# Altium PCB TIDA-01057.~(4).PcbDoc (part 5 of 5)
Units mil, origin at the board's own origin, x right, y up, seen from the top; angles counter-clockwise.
Board outline 4448 x 3930 mil, 4 copper layers (Layer 1 - Top Layer, Layer 2 - GND, Layer 3 - PWR, Layer 4 - Bottom Layer), stack 59.034 mil thick; 537 components, 284 nets, 1540 pads, 770 vias.
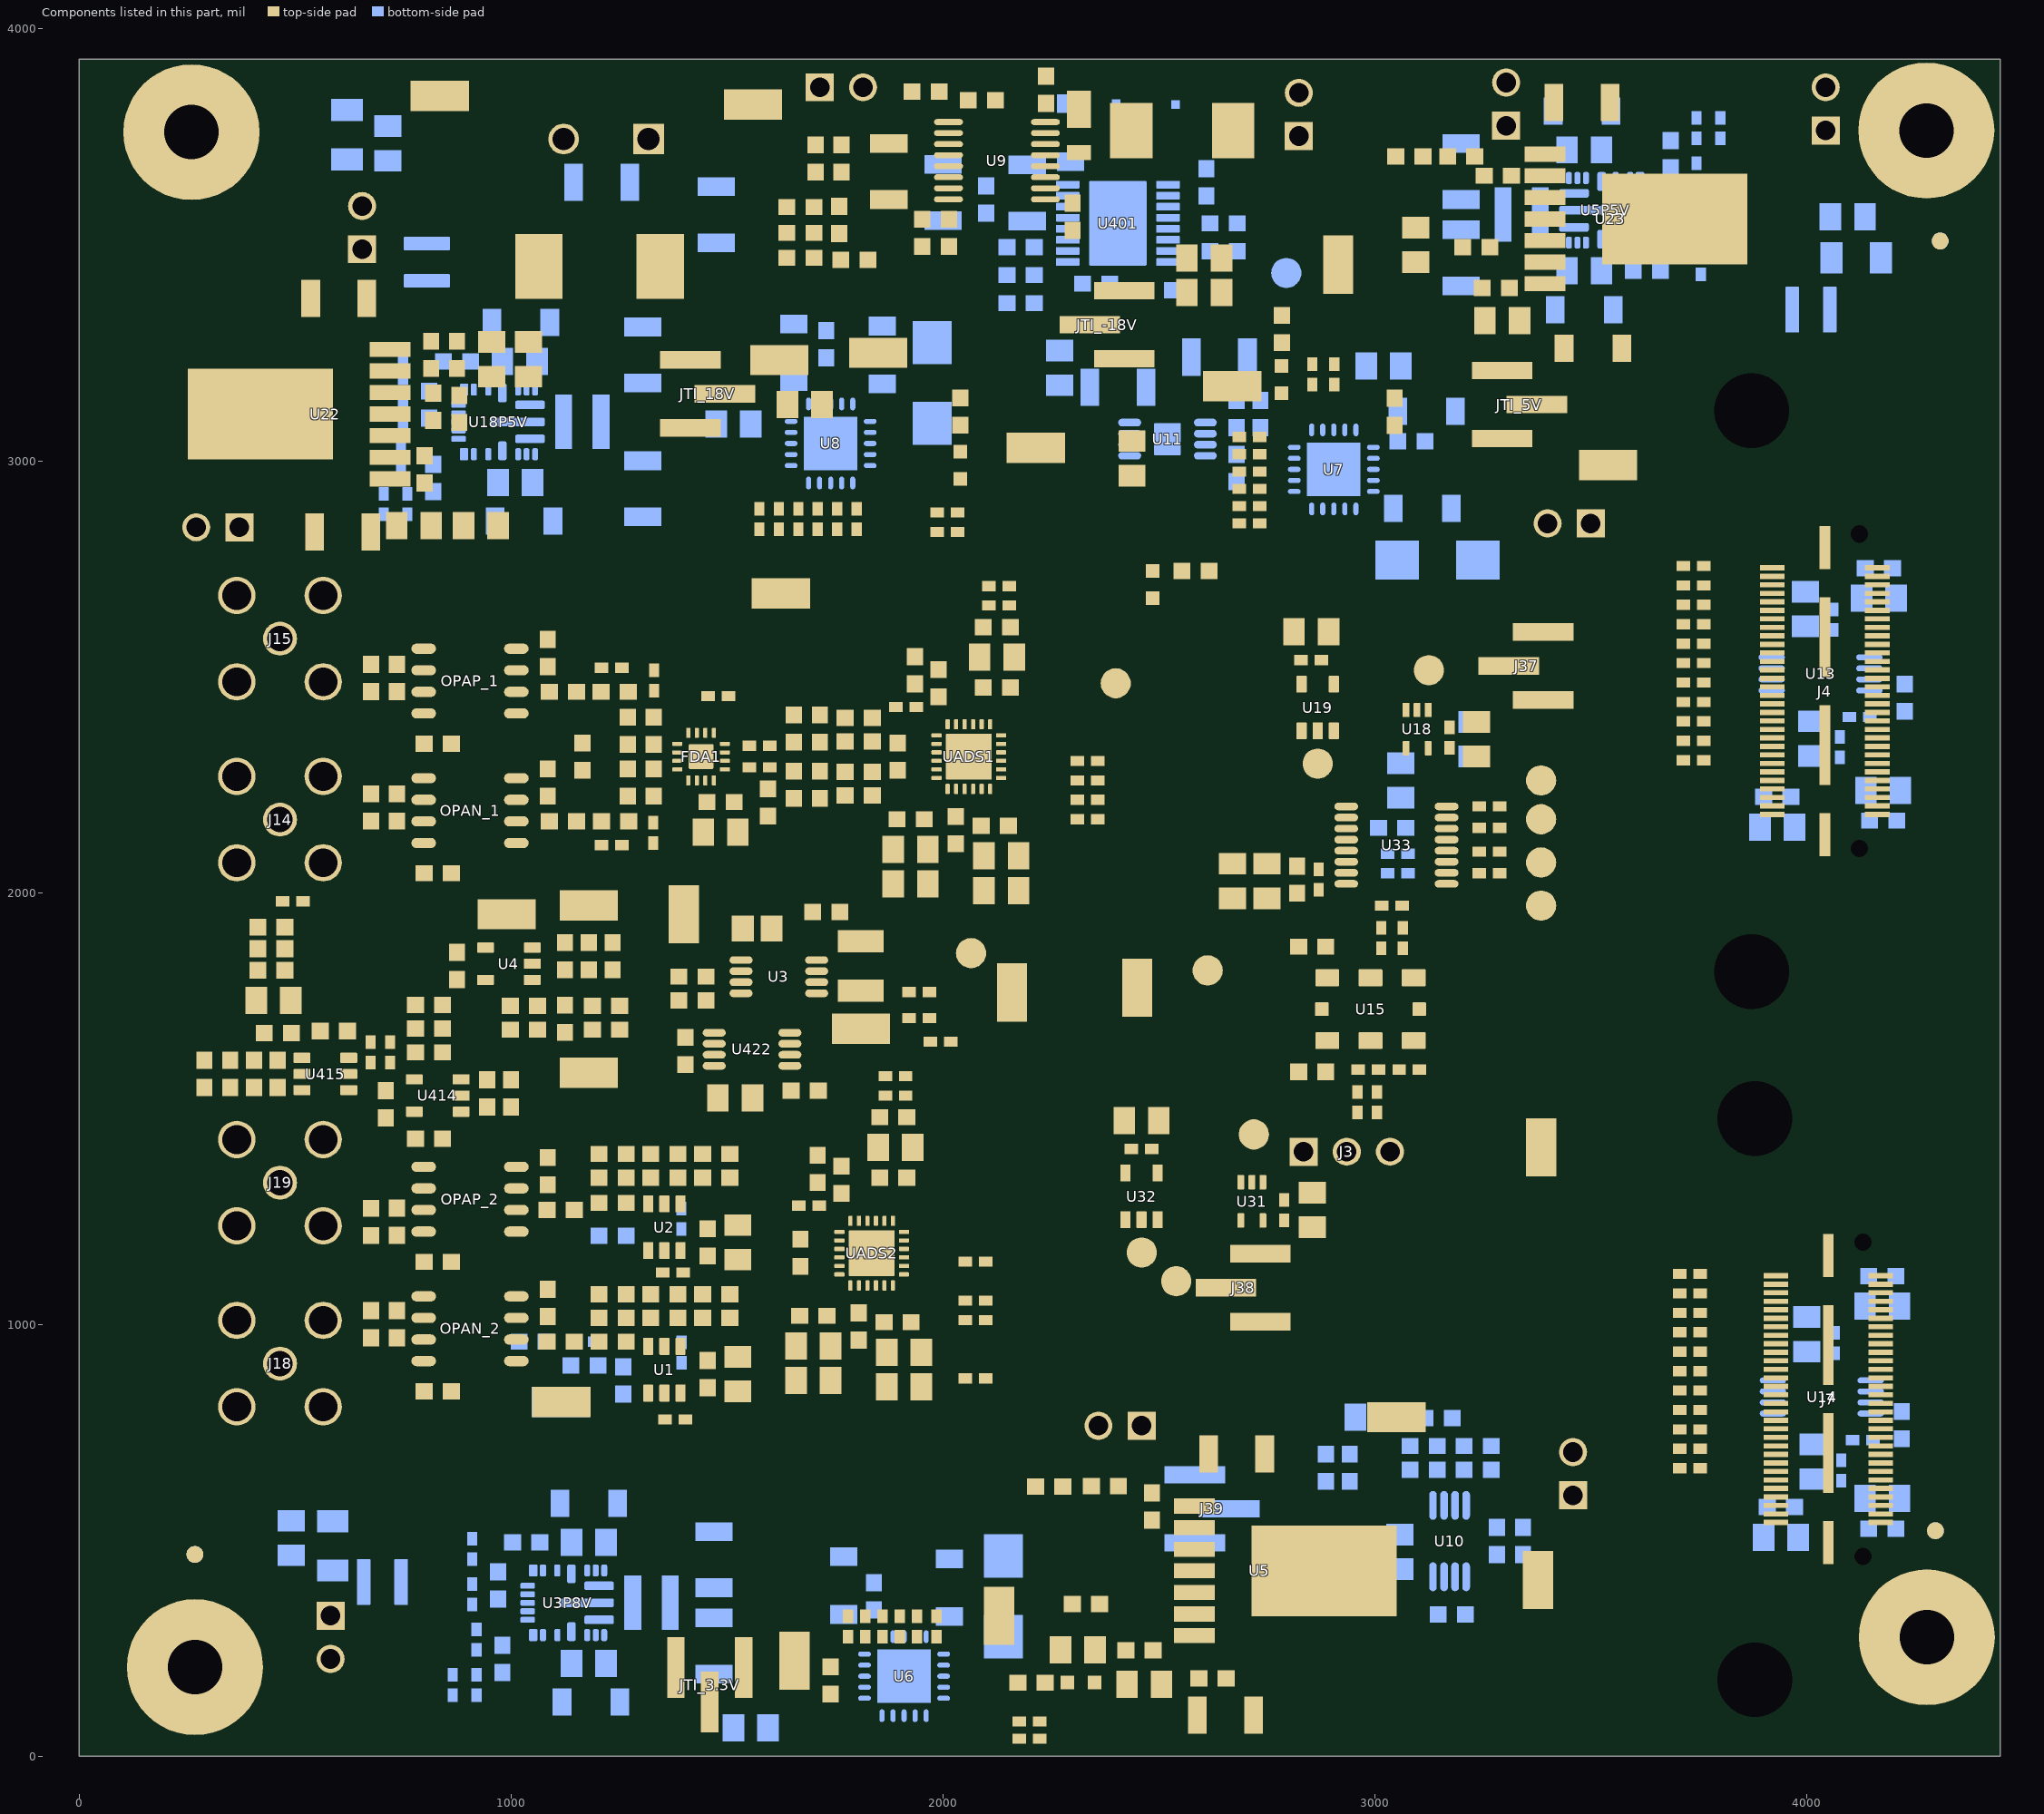
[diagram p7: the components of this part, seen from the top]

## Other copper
Layer 1 - Top Layer:
  rectangle net NetC40_2: 2219,3779 2257.6,3847
  rectangle net +18V: 1975,3110 2075,3190
  rectangle net NetC387_2: 1159.96,3025 1385,3150
  rectangle net NetC363_2: 1385,315 1510,395
  rectangle net NetJTI_3.3V_2: 1370,25 1490,120
  rectangle net 3.8V: 1629,240 1762,290
  region net PRE: 2205,3770.85 2205,3722 2272,3722 2279,3729 2279,3738 2441,3738 2441,3829.79 2376.21,3829.79 2293,3913 2291,3911 2217,3911 2217,3862.32 2220.32,3859 2284,3859 2284,3854 2284,3772
  region net GND: 2249.49,3669 2277,3669 2297,3689 2552,3689 2552,3646 2549,3643 2548.1,3643.9 2264.1,3643.9 2249.49,3643.9
  region net GND: 3335,3580 3288,3580 3288,3547 3115,3547 3108.55,3540.55 3146.59,3502.5 3214.48,3502.5 3234.49,3519 3317.54,3519 3335,3536.46
  region net NetC452_1: 439,1943 352,1943 352,1649 351,1648 256,1648 256,1588 261,1583 263,1585 431,1585 431,1638.78 442.22,1650 452,1650 452,1703 439,1716
  region net GND: 1660,3490 1660,3445 1540,3445 1540,3655 1605,3655 1605,3490
  region net NetC403_2: 2350,3260 2350,3210 2560,3210 2575,3225 2575,3345 2445,3345 2430,3330 2430,3260
  region net NetJTI_-18V_2: 2420,3340 2420,3295 2405,3280 2300,3280 2300,3225 2145,3225 2145,3320 2165,3340
  region net 1050_-18V: 2590,3505 2590,3355 2270,3355 2270,3555 2330,3555 2330,3425 2540,3425 2540,3505
  region net GND: 2525,3831 2774,3831 2774,3650 2838,3650 2838,3515 2774,3515 2679,3515 2679,3355 2610,3355 2605,3360 2605,3515 2555,3515 2525,3545
  region net GND: 925,3220 1090,3220 1130,3180 1130,2820 940,2820 940,2885 1030,2885 1030,2990 1030,3161 925,3161
  region net GND: 210,2925.6 386.4,2925.6 520,2792 570,2792 570,2880 527,2880 527,2965 590,2965 590,3085 790,3085 800,3075 843.78,3075 921.89,2996.89 921.89,2928 1035,2928 1035,3221 907.2,3221 907.2,3125.64 590.86,3129.15 585,3135 585,3435 547.5,3465 290,3465 210,3385
  region net 1050_18V: 640,3420 740,3420 740,3295 790,3295 790,3325 1093.18,3325 1123.18,3270 1245,3270 1255,3260 1505,3260 1505,3195 1415,3195 1415,3205 1350,3205 1350,3195 1335,3180 1140,3180 1140,3200 1095,3245 905,3245 895,3255 790,3255 775,3240 640,3240
  region net AGND: 862.87,1539.75 965,1539.75 965,1409.75 925,1409.75 840,1409.75 840,1449.75 925,1449.75 925,1519.75 862.87,1519.75
  region net REFOUT: 1690,1509.75 1690,1719.75 1880,1719.75 1880,1649.75 1755,1649.75 1750,1644.75 1750,1509.75
  region net AGND: 1510,1609.75 1430,1609.75 1415,1624.75 1340,1624.75 1340,1559.75 1410,1489.75 1510,1489.75
  region net 5V: 1433.54,1694.75 1433.54,1639.75 1340,1639.75 1340,1694.75
  region net 5V: 1563,1817.75 1554,1808.75 1511,1808.75 1410,1909.75 1410,2014.75 1563,2014.75
  region net 5V: 1915,1984.75 1845,1984.75 1835,1994.75 1835,2041.75 1845,2051.75 1915,2051.75
  region net 3.3V: 2053.93,291.07 2053.93,177.07 2083.93,147.07 2193.93,147.07 2193.93,291.07
  region net VDDO: 3194,2062.75 3092,2062.75 3075,2079.75 3075,2159.75 3099,2183.75 3194,2183.75 3194,2164.75 3128,2164.75 3115,2151.75 3115,2091.75 3126,2080.75 3194,2080.75
  region net -18.5V: 2125,3072.5 2125,2977.5 2125,2912.5 2260,2912.5 2260,2977.5 2360,2977.5 2360,3072.5
  region net 3.3V: 2732.21,1257.75 2732.21,1222.75 2760.21,1194.75 2900.21,1194.75 2910.21,1204.75 2910.21,1250.75 2903.21,1257.75
  region net GND: 2775.21,1269.75 2900.21,1269.75 2910.21,1279.75 2910.21,1329.75 2900.21,1339.75 2810.21,1339.75 2775.21,1304.75
  region net 3.3V: 2453,1326.3 2453,1516.75 2438.45,1531.3 2391.55,1531.3 2380,1519.75 2380,1356.13 2409.83,1326.3
  region net GND: 2466.83,1393.3 2501.83,1393.3 2529.83,1421.3 2529.83,1521.3 2519.83,1531.3 2480.83,1531.3 2466.83,1517.3
  region net 3.3V: 3114.81,2351.57 3272.81,2351.57 3272.81,2278.57 3257.81,2263.57 3144.81,2263.57 3114.81,2293.57
  region net GND: 2859.81,2525.57 2894.81,2525.57 2922.81,2553.57 2922.81,2656.94 2915,2664.75 2870,2664.75 2859.81,2654.55
  region net 3.3V: 2847.81,2458.57 2847.81,2656.94 2840,2664.75 2780,2664.74 2772.81,2657.55 2772.81,2503.57 2817.81,2458.57
  region net AGND: 1731.37,1808.16 1731.37,1975.16 1596.79,1975.16 1576.79,1955.16 1576.79,1868.16 1636.79,1808.16
  region net NetC5_2: 1863.15,1859.75 1863.15,1881.6 1863.15,1914.75 1817.31,1914.75 1775,1974.75 1740,1974.75 1740,1859.75
  region net NetC5_1: 1680.79,1802.16 1870,1802.16 1870,1734.75 1701.2,1734.75 1680.79,1755.16
  region net AGND: 1403.79,1829.16 1409.79,1823.16 1409.79,1730.16 1355.79,1730.16 1344.79,1741.16 1344.79,1770.16 1344.79,1819.75 1354.2,1829.16
  region net AGND: 1210,1715.01 1170,1715.01 1165,1720.01 1165,1760.01 1150,1775.01 1105,1775.01 1090,1790.01 1090,1811.01 1079,1822.01 1029,1822.01 1029,1847.01 1193,1847.01 1200,1840.01 1200,1790.01 1210,1780.01
  region net 5V: 1380,1179.75 1580,1179.75 1580,1124.75 1380,1124.75
  region net AGND: 1580,1199.75 1435,1199.75 1435,1239.75 1455,1259.75 1570,1259.75 1580,1249.75
  region net +24VDC: 1295,3360 1500,3360 1500,3515 1295,3515
  region net AGND: 1988,902.74 1995,909.75 1995,979.74 1950,1024.74 1914.45,1024.74 1905,1024.74 1905,984.75 1925,964.75 1925,902.74
  region net 5V: 1380,859.75 1395,874.75 1576.87,874.75 1610,901.75 1613.12,835.08 1580,819.75 1380,819.75
  region net AGND: 1580,894.75 1435,894.75 1435,934.75 1455,954.75 1570,954.75 1580,944.75
  region net AGND: 1610,917.75 1610,1014.75 1635,1039.75 1690,1039.75 1690,917.75
  region net 5V: 1610,834.75 1690,834.75 1690,901.75 1610,901.75
  region net NetC119_1: 1780,1102.75 1780,1009.75 1785,1004.75 1795,1004.75 1825,1004.75 1825,1054.75 1811,1068.75 1811,1102.75
  region net 3.3V: 1985,819.74 1925,819.74 1925,886.74 1982.45,886.74 1994.45,874.75 1994.45,829.19
  region net AGND: 1895,1319.75 1945,1319.75 1975,1349.75 1975,1444.75 1895,1444.75
  region net VDD: 2962,2036.75 2726,2036.75 2718,2044.75 2718,2112.75 2788,2182.75 2962,2182.75 2962,2112.75 2898,2112.75 2885,2099.75 2885,2069.75 2900,2054.75 2962,2054.75
  region net GND: 2635.01,2039.75 2635.01,2114.75 2645.01,2124.75 2692.01,2124.75 2702.01,2114.75 2702.01,2039.75
  region net 3.3V: 2635.01,2014.75 2635.01,1944.75 2645.01,1934.75 2775.01,1934.75 2785.01,1944.75 2785.01,2014.75
  region net 5V: 1475,2271.75 1475,2109.75 1465,2099.75 1395,2099.75 1395,2214.75 1405,2224.75 1405,2271.75
  region net AGND: 1495,2229.75 1495,2109.75 1505,2099.75 1580,2099.75 1615,2134.75 1615,2199.75 1570,2199.75 1560,2209.75 1560,2229.75
  region net NetFDA1_13: 1475,2357.75 1475,2469.75 1425,2469.75 1405,2449.75 1405,2357.75
  region net AGND: 1835,2067.75 1835,2164.75 1860,2189.75 1915,2189.75 1915,2067.75
  region net NetC88_2: 2005,2252.75 2005,2159.75 2010,2154.75 2020,2154.75 2050,2154.75 2050,2204.75 2036,2218.75 2036,2252.75
  region net AGND: 2219.45,2052.74 2219.45,2149.74 2194.45,2174.74 2139.45,2174.74 2130,2174.74 2130,2134.75 2150,2114.75 2150,2052.74
  region net 3.3V: 2220,1972.75 2150,1972.75 2150,2036.74 2220,2036.74
  region net AGND: 2135,2454.75 2185,2454.75 2215,2484.75 2215,2579.75 2135,2579.75
  region net GND: 3157.81,2365.54 3272.81,2365.54 3272.81,2485.04 3210,2485.04 3157.81,2432.85
  region net GND: 4045.03,1236.69 4065.03,1236.69 4065.03,1101.69 4095.03,1071.7 4095.03,576.7 4065.03,546.7 4065.03,416.69 4045.03,416.7 4035.03,426.7 4005.03,456.69 4005.03,1196.69 4035.03,1226.69
  region net GND: 2400,2992.5 2475,2992.5 2490,3007.5 2490,3082.5 2500,3092.5 2540,3092.5 2551.07,3081.43 2551.07,3018.57 2574.79,2994.85 2589.79,2979.85 2589.79,2933.5 2400,2933.5
  region net GND: 4036.51,2056.79 4056.51,2056.79 4056.51,2191.78 4087.01,2222.28 4087.01,2716.29 4056.51,2746.78 4056.51,2876.79 4036.51,2876.78 4026.51,2866.78 3996.52,2836.79 3996.52,2096.79 4026.51,2066.79
  region net 5V: 1392.4,840.61 1410,823.01 1410,786.12 1403.62,779.75
  region net 5V: 597.5,1639.75 682.5,1639.75 682.5,1714.75 597.5,1714.75
  region net AGND: 822.5,1754.75 905,1754.75 905,1664.75 822.5,1664.75
  region net GND: 2870,3585 3015,3585 3015,3515 3130,3515 3130,3562.78 3075,3587.22 3075,3725 3020.02,3725 3020.02,3695 2870,3695
  region net 1050_-18V: 1830,3600 1920,3600 1920,3520 2092,3520 2092,3865 2175,3865 2175,3520 2300,3520 2300,3454 1805,3454 1805,3485 1830,3485
  region net NetC31_1: 1675.16,3905.16 1675,3705 1925,3705 1925,3815 1760.02,3815 1760.08,3905.16
  region net NetCin3_1: 2419.84,815 2419.84,690.84 2407,678 2379,678 2379,592 2379,580 2387,580 2524,580 2525,579 2525,561 2656,561 2657,561 2660,563 2660,759 2532,759 2532,763 2532,766 2532,815
  region net 1050_3.3V: 2630,294 2630,217 2611,198 2611,30 2480,30 2480,212 2466,226 2466,263 2503,263 2536,296
  region net GND: 3089,535 2855.7,615 2773,615 2773,757 2699,757 2699,535 2699,474 2674,449 2555,449 2530,449 2365.83,449 2281.76,520 2277.5,586.5 2252,599 2233,599 2233,615 2212.4,615 2197,615 2197,565.88 2235.88,565.88 2237.76,200 2306.76,200 2306.76,353.61 2366.15,413 2535.2,413 2654,413 2654,50 2814,50 3089,325
  region net 1050_3.3V: 1508.67,265 1588.67,265 1588.67,157.84 1683.5,63 1693,63 1832,63 1839.91,50 1964.67,50 1964.67,10 1508.67,10
  region net NetCin2_1: 3465,3875 3465,3685 3335,3685 3275,3685 3275,3640 3210,3640 3210,3829.96 3344.96,3829.96 3390,3875
  region net 1050_5V: 3445,3430 3290,3430 3290,3370 3300,3360 3300,3275 3270,3275 3225,3230 3225,3185 3455,3185 3460,3190 3460,3315 3445,3330
  region net GND: 3890,3665 3890,3740 3857.34,3740 3857.34,3665 3639.69,3665 3639.33,3664.65 3595,3708.98 3595,3875 3484.67,3875 3485.39,3580 3335,3580 3335,3540 3484.67,3540 3484.67,3220 3520.63,3220 3595,3220 3595,3385 3665,3455 3857.34,3455 3857.34,3414.69 3890,3414.69
  region net NetJTI_5V_2: 3445,3095 3155,3095 3155,3185 3035,3185 3035,3275 3040,3280 3185,3280 3210,3255 3210,3180 3220,3170 3445,3170
  region net NetC374_2: 3210,3085 3210,3015 3215,3010 3435,3010 3465,3040 3695,3040 3695,3205 3470,3205 3470,3180 3460,3170 3460,3085
  region net NetC363_2: 1355,395 1355,135 1410,135 1410,395
  region net NetJTI_18V_2: 1565,3175 1420,3175 1420,3105 1495,3105 1495,3050 1565,3050 1565,3105
  region net 18.5V: 1553,3278 1548,3273 1548,3195.46 1703.46,3195.46 1711,3203 1711,3265.5 1698.5,3278
  region net NetCin1_1: 670,2980 665.8,2980 665.8,3055 596.03,3055 596.03,2933.55 665.8,2933.55 675,2924.35 675,2906.74 650,2881.74 650,2790 765,2790 765,2915 820,2915 820,2980
  text ".Layer_Name" at 57,-1078.49 h60
Layer 2 - GND:
  pour cut-out: 205.85,2897.37 410,2897.37 410,2894.99 480,2824.99 480,2780 212.11,2780 205,2787.11
  text ".Layer_Name" at 57,-1078.49 h60
Layer 3 - PWR:
  rectangle net +24VDC: 1390,3365 1493,3535
  rectangle net +18V: 1925,3115 2025,3190
  region net NetC387_2: 1385,3140 1225,3140 1225,3035 1385,3035
  rectangle net NetC374_2: 3130,3515 3285,3620
  rectangle net NetC381_1: 509,2880 579,2966
  rectangle net NetC401_1: 2617,3676 2886,3795
  rectangle net NetC374_2: 3495,3075 3685,3205
  rectangle net 1050_3.3V: 1790,0 2624,50
  rectangle net 1050_3.3V: 1975,45 2624,96
  rectangle net NetCin1_1: 330,2795 410,2870
  region net GND: 1265,3625 1435,3625 1470,3660 1470,3740 1435,3775 1265,3775
  text ".Layer_Name" at 57,-1078.49 h60
Layer 4 - Bottom Layer:
  rectangle net GND: 3585.29,3637 3637,3657.8
  rectangle net NetC367_1: 4010,3285 4090,3810.08
  rectangle net GND: 690,3025 729.5,3090
  rectangle net GND: 3760,3575 3800,3635
  rectangle net GND: 865,295 895,355
  rectangle net GND: 3415,3610 3434.61,3620
  rectangle net GND: 3585,3636.75 3603,3727.21
  rectangle net GND: 1061,214 1081,328
  rectangle net GND: 902,2825 920,2969.61
  region net NetC403_2: 2475,3655 2335,3655 2335,3450 2475,3450
  rectangle net NetJTI_5V_2: 3035,3185 3160,3275
  rectangle net NetC357_1: 1120,400 1155,505
  rectangle net NetC363_2: 1355,295 1528.31,415
  rectangle net NetC357_1: 1095,210 1155,315
  region net NetC374_2: 3320,3635 3145,3635 3145,3505 3320,3505
  region net NetC369_1: 3570,3700 3505,3700 3505,3620 3570,3620
  region net NetC369_1: 3545,3535 3510,3535 3510,3445 3545,3445
  rectangle net NetC387_2: 1154.96,3020 1345,3145
  rectangle net NetC381_1: 965,3115 995,3205
  rectangle net NetC381_1: 940,2890 995,3030
  rectangle net NetC387_2: 1205,2955 1315,3030
  rectangle net NetC387_2: 1235,3125 1340,3185
  rectangle net NetJTI_18V_2: 1445,3040 1520,3140
  region net GND: 3004,484 3004,583 3000,587 2955,587 2955,486.52 2957.52,484
  region net -0.2V: 2985,825 2865,825 2661.88,680 2510,680 2510,625 2730,625 2865,680 2985,680
  region net GND: 4105,3611.19 4105,3290 4200,3290 4215,3305 4210,3580 4160,3600
  region net GND: 880,3030 905,3030 905,3050 925,3050 925,3000 880,3000
  region net 5V: 910,1773.98 910,1829.75 985,1829.75 985,1773.98
  region net -18V: 2635,3110 2763.54,3110 2763.54,3227.46 2763.54,3295.12 2610,3295.12 2610,3145 2578.96,3145 2578.96,3082.29 2635,3082.29
  region net GND: 2416,3136 2416,3127.95 2470,3127.95 2470,2925 2708.54,2925 2708.54,2978.54 2640,2978.54 2640,3020 2560,3020 2560,3155 2600,3155 2600,3234 2600,3285.12 2565.12,3285.12 2540.12,3285.12 2540.12,3230 2467.5,3230 2455,3215 2416,3215
  region net GND: 728.35,3105 781.46,3105 791.46,3115 830,3115 830,3080 765,3015 723.07,3015 723.07,3105
  region net GND: 3675.41,3560.39 3728.19,3560.39 3728.58,3560 3770,3560 3770,3655 3735,3655 3675.26,3575.29
  region net NetC401_1: 2315,3532.87 2120.02,3532.87 2120.02,3380 2011.1,3380 1935,3485 1935,3590 1937.72,3592.72 2315,3592.72
  region net NetC385_2: 950,3099.94 1069.57,3100.09 1092.94,3123.46 1135,3123.46 1135,3060 1090.5,3060 1070.5,3080 950,3080
  region net GND: 935,3100 902,3100 902,3050 1078.87,3050 1057.87,3071 935,3071
  region net NetC361_2: 1130,364.92 1249.55,365.08 1269.48,385 1295,385 1295,325 1270.5,325 1250.5,345 1130,345
  region net GND: 1105,363 1061,363 1061,320 1242.59,320 1226.59,336 1222.96,336 1105,336
  region net GND: 3560,3575 3603,3575 3603,3615 3422.41,3615 3438.41,3599 3442.04,3599 3560,3599
  region net NetC373_2: 3555,3570.12 3434.97,3569.97 3425,3560 3365,3560 3365,3600 3425.02,3600 3435.02,3590 3555,3590
  region net GND: 1240,3595 1240,3760 1335,3855 1505,3855 1525,3835 1525,3605 1300,3605 1290,3595
  region net +24VDC_IN: 1185,3760 1160,3785 1015,3785 880,3650 880,3420 1160,3420 1185,3445
  region net 3.3V: 3020,2270.04 3250,2270.04 3260,2280.04 3260,2345.04 3040.3,2345.04 3020,2324.75
  region net VDDO: 3115,2049.75 3095,2029.75 3060,2029.75 3060,2114.75 3050,2124.75 3050,2169.75 3020,2199.75 3020,2244.75 3090,2244.75 3115,2219.75
  region net GND: 3260,2369.75 3260,2474.75 3250,2484.75 3200,2484.75 3190,2474.75 3190,2369.75
  region net AGND: 1210,859.75 1280,859.75 1280,809.75 1210,809.75
  region net AGND: 1153.5,1226.24 1223.5,1226.24 1223.5,1176.24 1153.5,1176.24
  region net NetC33_1: 2945.52,464 3122.02,464 3143.02,443 3143.02,383 2988.02,383 2945.52,425.5
  region net 3.3V: 3021.04,486 3086.04,486 3096.04,496 3096.04,558 3086.04,568 3031.04,568 3021.04,558
  region net GND: 989.51,375 890,375 890,277.13 946.3,277.13 946.3,296.3 989.51,339.51
  pour cut-out: 728.35,3120 705,3120 705,3005.49 705.49,3005 735,3005 735,3120
  pour cut-out: 3766.65,3670 3790,3670 3790,3540 3765.06,3540
  pour cut-out: 899.51,390 875,390 875,270.49 899.51,270.49
  region net -18.5V: 2385,3205 2385,3075 2382.5,3072.5 2360,3072.5 2360,2950 2195,2950 2195,3205
  region net NetJTI_-18V_2: 2145,3295 2145,3225 2437.77,3225 2457.77,3245 2490,3245 2490,3285 2490,3295
  region net NetJTI_3.3V_2: 1508.67,93.5 1478.5,93.5 1425.53,88.68 1405,75 1405,30 1510,30
  region net GND: 2130,3450 2165,3450 2165,3325 2040,3325 2040,3365 2130,3365
  region net NetC379_1: 573.74,3725 765,3725 765,3625 864.02,3525.98 864.02,3480 745,3480 725,3500 685,3540 585,3540 575,3550
  region net NetC355_1: 447,493 681,493 681,289 678,286 509,286 509,344 447,406
  text ".Layer_Name" at 57,-1078.49 h60

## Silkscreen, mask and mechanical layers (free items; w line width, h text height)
Top Overlay:
  lines w10: 1555,999.75 1595,959.75 1595,700 ; 1305,565 1305,700 1680,700 1680,565 1305,565
  lines w20: 910,3560 960,3560 ; 935,3535 935,3585 ; 1465.69,3562.89 1515.69,3562.89
  text "+24VDC" at 765,3710 h30
  text "+5.5V" at 2840,3550 h30
  text "JMTO_-18V" at 2165,3380 h20
  text "+18.5V" at 1551.07,3283.29 h30
  text "JZO_5V" at 3160,3241 h20
  text "-18V" at 2600,3230 h30
  text "JZO_18V" at 1205,3223 h20
  text "JPRO_-18V" at 2163,3221 h20
  text "+18V" at 1935,3205 h30
  text "JSO_18V" at 1205,3057 h20
  text "JSO_5V" at 3160,2992 h20
  text "-18.5V" at 2135,2910 h30
  text "SYSCLK0" at 3530,2250 h30
  text "SYSCLK1" at 3530,2150 h30
  text "SYSCLK2" at 3530,2050 h30
  text "5V" at 1340,2005 h30 r90
  text "SYSCLK3" at 3530,1950 h30
  text "CONVST" at 2310,1044.75 h30
  text "-0.2V" at 3141,775 h30
  text "3.3V" at 2085,310 h30
  text "JSO_3.3V" at 1392,286 h20 r90
  text "JZO_3.3V" at 1553,283.5 h20 r90
  text "3.8V" at 1638,106 h30
  text ".Layer_Name" at 57,-1078.49 h30
Bottom Overlay:
  text "+18V" at 2160,3125 h30
  text "3.3V" at 2230,250 h30 r270
  text ".Layer_Name" at 57,-1078.49 h30
Top Paste:
  text ".Layer_Name" at 57,-1078.49 h60
Bottom Paste:
  text ".Layer_Name" at 57,-1078.49 h60
Top Solder:
  text ".Layer_Name" at 57,-1078.49 h60
  text ".Layer_Name" at 57,-1078.49 h60
Bottom Solder:
  text ".Layer_Name" at 57,-1078.49 h60
Drill Guide:
  text ".Layer_Name" at 57,-1078.49 h60
M1 Board Outline:
  lines w10: 0,0 4448,-1 4448,3929 0,3930 0,0
  text ".Layer_Name" at 57,-1078.49 h60
M2 Board Dimensions:
  rectangle: -395,-620 -20,-495
  rectangle: -520,-495 -395,-370
  lines w7: -520,-495 480,-495 ; -395,-620 -395,-370 ; -270,-620 -270,-370 ; -20,-620 -20,-370 ; 230,-620 230,-370 ; -520,-620 -520,-370 480,-370 480,-620 -520,-620
  text ".Layer_Name" at 57,-1078.49 h60
M3 3D STEP Top:
  text ".Layer_Name" at 57,-1078.49 h60
M4 3D STEP Bottom:
  text ".Layer_Name" at 57,-1078.49 h60
M5 Assembly Top:
  lines w10: -812,-1150.17 5788,-1150.17 ; -812,-946.83 5790,-946.83 ; -812,-743.5 -812,-1353.5 3193,-1353.5 5790,-1353.5 5790,-743.5 -811.5,-743.5 -811.5,-1353.5 764,-1353.5 ; 1653,-1353.5 1653,-743.5 ; 2920,-946.83 2920,-743.5 ; 3760,-946.83 3760,-743.5 ; 4382,-1360 4382,-1157.17
  text ".VariantName" at 1064,3366 h60
  text "COMPONENTS MARKED 'DNP' SHOULD NOT BE POPULATED." at 633.5,-538.5 h60
  text "ASSEMBLY VARIANT:" at 633,-654 h60
  text "PCB VIEWED FROM TOP SIDE" at -748.5,-875.67 h60
  text "BOARD #:" at 1728,-875.67 h60
  text ".PRJ_Number" at 2273.5,-875.67 h60
  text "REV:" at 3118,-875.67 h60
  text ".PCB_Rev" at 3409.5,-875.67 h60
  text "SVN REV:" at 3956,-875.67 h60
  text ".VersionControl_RevNumber" at 4462,-875.67 h60
  text "TID #:" at 1728,-1079 h60
  text ".TID" at 2273.5,-1079 h60
  text "PLOT NAME =" at -748.5,-1284.34 h60
  text ".plot_File_Name" at 57,-1284.34 h60
  text "GENERATED    :" at 1730,-1284.34 h60
  text ".Print_Date" at 2599.5,-1284.34 h60
  text ".Print_Time" at 3328.5,-1284.34 h60
  text "TEXAS INSTRUMENTS" at 4593,-1284.34 h60
M6 Assembly Bottom:
  lines w10: -812.5,-947.33 5789.5,-947.33 ; -810.5,-1150.67 5789.5,-1150.67 ; 595.5,-1360.5 595.5,-1157.67 ; 1217.5,-947.33 1217.5,-744 ; 2057.5,-947.33 2057.5,-744 ; 3324.5,-1354 3324.5,-744 ; 4213.5,-1354 5789,-1354 5789,-744 -812.5,-744 -812.5,-1354 1784.5,-1354 5789.5,-1354 5789.5,-744
  text "COMPONENTS MARKED 'DNP' SHOULD NOT BE POPULATED." at 5582,-538 h60
  text ".VariantName" at 4538,-654 h60
  text "ASSEMBLY VARIANT:" at 5577,-654 h60
  text ".VersionControl_RevNumber" at 515.5,-876.17 h60
  text "SVN REV:" at 1021.5,-876.17 h60
  text ".PCB_Rev" at 1568,-876.17 h60
  text "REV:" at 1859.5,-876.17 h60
  text ".PRJ_Number" at 2704,-876.17 h60
  text "BOARD #:" at 3249.5,-876.17 h60
  text "PCB VIEWED FROM BOTTOM SIDE" at 5726,-876.17 h60
  text ".TID" at 2704,-1079.5 h60
  text "TID #:" at 3249.5,-1079.5 h60
  text "TEXAS INSTRUMENTS" at 384.5,-1284.84 h60
  text ".Print_Time" at 1649,-1284.84 h60
  text ".Print_Date" at 2378,-1284.84 h60
  text "GENERATED    :" at 3247.5,-1284.84 h60
  text ".plot_File_Name" at 4920.5,-1284.84 h60
  text "PLOT NAME =" at 5726,-1284.84 h60
M9 Title Sheet:
  drawing of 56 lines, arcs and shapes, not listed
  text "1" at 219.84,7816.5 h70
  text "2" at 2715.5,7816.5 h70
  text "3" at 5204.84,7816.5 h70
  text "4" at 7711.51,7816.5 h70
  text "5" at 10210.5,7816.5 h70
  text "6" at 12715.5,7816.5 h70
  text "A" at -936.5,6673.5 h70
  text "A" at 13863.5,6673.5 h70
  text "B" at -936.5,4293.5 h70
  text "B" at 13863.5,4293.5 h70
  text "C" at -936.5,1918.5 h70
  text "C" at 13863.5,1918.5 h70
  text "PROJECT TITLE:" at 10823.5,57.5 h45
  text ".PRJ_Title" at 10873.5,-75.83 h70
  text "DESIGNED FOR:" at 10823.5,-243.5 h45
  text ".PRJ_Customer" at 10873.5,-383.5 h70
  text "D" at -936.5,-451.5 h70
  text "D" at 13863.5,-451.5 h70
  text "FILE NAME:" at 10823.5,-543.5 h45
  text ".PCB_File_Name_No_Path" at 10873.5,-663.5 h70
  text "Texas Instruments (TI) and/or its licensors do not warrant the accuracy or completeness of this specification" at 5854,-825.34 h45
  text "ENGINEER:" at 10823.5,-833.5 h45
  text "LAYOUT BY:" at 12328.5,-833.5 h45
  text "or any information contained therein. TI and/or its licensors do not warrant that this design will meet" at 5809.01,-938 h45
  text ".PRJ_Engineer" at 10873.5,-988.49 h70
  text "the specifications, will be suitable for your application or fit for any particular purpose, or will operate in" at 5809.01,-1050.67 h45
  text ".Layer_Name" at 57,-1078.49 h60
  text "ALTIUM DESIGNER VERSION:" at 12328.5,-1143.5 h45
  text "an implementation. TI and/or its licensors do not warrant that the design is production worthy. You should" at 5809.01,-1163.33 h45
  text "completely validate and test your design implementation to confirm the system functionality for your application." at 5854,-1276 h45
  text ".print_Scale" at 10873.5,-1276.83 h70
  text ".Application_BuildNumber" at 12379,-1276.83 h70
  text "1" at 219.84,-1483.5 h70
  text "2" at 2715.5,-1483.5 h70
  text "3" at 5204.84,-1483.5 h70
  text "4" at 7711.51,-1483.5 h70
  text "5" at 10210.5,-1483.5 h70
  text "6" at 12715.5,-1483.5 h70
M10 Fab Notes:
  drawing of 173 lines, arcs and shapes, not listed
  text "DESIGN INFORMATION" at 11857.02,5981 h60
  text "MIN. TRACK WIDTH:" at 11212.46,5801 h60
  text "8" at 12308.7,5801 h60
  text "MIL" at 12463.46,5801 h60
  text "MIN. CLEARANCE:" at 11212.46,5669 h60
  text "mm" at 12463.46,5669 h60
  text ".127" at 12200,5665 h60
  text "MIN. VIA PAD SIZE:" at 11212.46,5537 h60
  text "20" at 12278.71,5537 h60
  text "MIL" at 12463.46,5537 h60
  text "0.05mm (2MIL)" at 11907.46,5395.29 h60
  text "MINIMUM ANNULAR RING" at 10883.23,5391 h60
  text "EXTERNAL" at 12615.46,5391 h60
  text "PER" at 11083.23,5273 h60
  text "IPC-D-275 CLASS 2 LEVEL C" at 11303.23,5273 h60
  text "MIL, HOLES" at 12791.46,5160.71 h60
  text "+/-" at 12399,5160 h60
  text "+/-" at 13253,5160 h60
  text "REGISTRATION TOLERANCES:" at 10883.23,5155 h60
  text "METAL" at 12083,5155 h60
  text "5" at 12659.2,5155 h60
  text "3" at 13492.2,5155 h60
  text "MIL" at 13608.46,5155 h60
  text "+/-" at 13253,5042 h60
  text "HOLE SIZE TOLERANCE (UNLESS OTHERWISE SPECIFIED):" at 10883.23,5037 h60
  text "3" at 13492.2,5037 h60
  text "MIL" at 13608.46,5037 h60
  text "MATERIAL:" at 10808.46,4827.54 h60
  text "FR-4 High Tg" at 11794.9,4687.21 h60
  text "FR-408" at 11229.46,4678.64 h60
  text "OTHER" at 12717.46,4678.64 h60
  text "X" at 11640,4675 h60
  text "62 MIL (1.6mm) +/-10%" at 11549.56,4515.92 h60
  text "THICKNESS:" at 10883.23,4511.64 h60
  text "X" at 11421.4,4511.64 h60
  text "OTHER" at 12834.46,4511.64 h60
  text "TOLERANCE:" at 10883.23,4353.64 h60
  text "X" at 11722.53,4353.64 h60
  text "ANSI IPC-6012 TYPE 3 CLASS 2" at 11909.48,4353.64 h60
  text "OTHER +/-" at 11909.46,4197.64 h60
  text "BOW & TWIST:" at 10883.23,4040.64 h60
  text "X" at 11722.53,4040.64 h60
  text "ANSI IPC-6012 TYPE 3 CLASS 2" at 11909.48,4040.64 h60
  text "OTHER +/-" at 11909.46,3882.13 h60
  text "DRILLING:" at 10808.46,3743.64 h60
  text "REFERENCE:" at 10883.23,3626.64 h60
  text "X" at 11531.46,3626.64 h60
  text "AS SHOWN" at 11718.46,3626.64 h60
  text "X" at 12432.46,3626.64 h60
  text "NC_DRILL FILES" at 12569.46,3626.64 h60
  text "PTH COPPER THICKNESS:" at 10883.23,3468.64 h60
  text "X" at 12013.46,3468.64 h60
  text "20-30 um" at 12150.46,3468.64 h60
  text "OTHER" at 12867.46,3468.64 h60
  text "BOARD FINISH:" at 10808.46,3309.64 h60
  text "SILKSCREEN:" at 10963.68,3191.64 h60
  text "X" at 11912.46,3191.64 h60
  text "TOP" at 12038.46,3191.64 h60
  text "X" at 12422.46,3191.64 h60
  text "BOTTOM" at 12549.46,3191.64 h60
  text "SILKSCREEN COLOR:" at 10963.68,3024.64 h60
  text "X" at 11911.42,3024.64 h60
  text "WHITE" at 12038.46,3024.64 h60
  text "OTHER" at 12549.46,3024.64 h60
  text "X" at 12042.42,2865.44 h60
  text "GREEN" at 12169.46,2865.44 h60
  text "OTHER" at 12787.46,2865.44 h60
  text "SOLDER RESIST COLOR:" at 10963.68,2854.64 h60
  text "X" at 12042.42,2695.44 h60
  text "MATTE" at 12169.46,2695.44 h60
  text "SEMI-GLOSS" at 12787,2694.8 h60
  text "IMMERSION GOLD (ENIG)" at 11869.46,2506.92 h60
  text "ENEPIG" at 13207,2503.64 h60
  text "SURFACE FINISH:" at 10808.46,2502.64 h60
  text "X" at 11682.51,2502.64 h60
  text "IMM. TIN/SILVER OR EQUIV" at 11138,2345.64 h60
  text "OTHER" at 12569.46,2345.64 h60
  text "ARRAY/PANEL:" at 10808.46,2166.64 h60
  text "CUT AND TRIM PER M1 BOARD OUTLINE" at 11869.46,2162.35 h60
  text "X" at 11680,2155 h60
  text "N.C. ROUTE" at 11869.46,2010.64 h60
  text "V. SCORE" at 12735.46,2010.64 h60
  text "CERTIFICATION:" at 10808.46,1873.64 h60
  text "MATERIALS AND WORKMANSHIP FOR ALL PCBS" at 11533.46,1873.64 h60
  text "TO MEET OR EXCEED THE REQUIREMENTS OF:" at 11533.46,1775.64 h60
  text "X" at 11159.96,1639.13 h60
  text "ANSI IPC-A-600F CLASS ->" at 11298.96,1639.13 h60
  text "X" at 12938.02,1639.13 h60
  text "2" at 13056.96,1639.14 h60
  text "1" at 12741.96,1637.64 h60
  text "3" at 13410.96,1637.64 h60
  text "X" at 11974.02,1479.64 h60
  text "RoHS" at 12110.96,1479.64 h60
  text "OTHER" at 12755.36,1479.64 h60
  text "PER ORDER" at 13152.42,1479.64 h60
  text "ALL BOARDS MUST MEET OR EXCEED UL94-V0 REQUIREMENTS." at 10836,1314 h60
  text "PCB MUST BEAR THE UL94V-0 UL REGISTERED MATERIAL ID NUMBER" at 10836,1194 h60
  text "ADDITIONAL REQUIREMENTS:" at 10808.46,1020.64 h60
  text "MICROSECTION:" at 10883.23,905.64 h60
  text "YES" at 11788.96,905.64 h60
  text "REQUIRED" at 12650.46,749.49 h60
  text "BARE BOARD ELEC. TEST:" at 10883.23,746.64 h60
  text "NONE" at 12188.96,746.64 h60
  text "X" at 12523.46,746.64 h60
  text "PER ORDER" at 13242.46,746.64 h60
  text ".Layer_Name" at 57,-1078.49 h60
M11 Gerber Information:
  lines w10: -812,-1150.17 5788,-1150.17 ; -812,-946.83 5790,-946.83 ; -812,-743.5 -812,-1353.5 3193,-1353.5 5790,-1353.5 5790,-743.5 -811.5,-743.5 -811.5,-1353.5 764,-1353.5 ; 1653,-1353.5 1653,-743.5 ; 2920,-946.83 2920,-743.5 ; 3760,-946.83 3760,-743.5 ; 4382,-1360 4382,-1157.17
  text "ALL ARTWORK VIEWED FROM TOP SIDE" at -748.5,-875.67 h60
  text "BOARD #:" at 1728,-875.67 h60
  text ".PRJ_Number" at 2273.5,-875.67 h60
  text "REV:" at 3118,-875.67 h60
  text ".PCB_Rev" at 3409.5,-875.67 h60
  text "SVN REV:" at 3956,-875.67 h60
  text ".VersionControl_RevNumber" at 4462,-875.67 h60
  text "LAYER NAME =" at -748.5,-1078.49 h60
  text "TID #:" at 1728,-1079 h60
  text ".TID" at 2273.5,-1079 h60
  text "PLOT NAME =" at -748.5,-1284.34 h60
  text ".plot_File_Name" at 57,-1284.34 h60
  text "GENERATED    :" at 1730,-1284.34 h60
  text ".Print_Date" at 2599.5,-1284.34 h60
  text ".Print_Time" at 3328.5,-1284.34 h60
  text "TEXAS INSTRUMENTS" at 4593,-1284.34 h60
M12 Stackup:
  drawing of 295 lines, arcs and shapes, not listed
  text "Layer" at 8787.5,7612.5 h60
  text "Name" at 9197.41,7612.5 h60
  text "Material" at 10607,7612.5 h60
  text "Thickness" at 11466.77,7612.5 h60
  text "Constant" at 12116.6,7612.5 h60
  text "Board Layer Stack" at 12686.47,7612.5 h60
  text "1" at 8787.5,7492.5 h60
  text "Top Overlay" at 9197.41,7492.5 h60
  text "2" at 8787.5,7372.5 h60
  text "Top Solder" at 9197.41,7372.5 h60
  text "Solder Resist" at 10607,7372.5 h60
  text "0.40mil" at 11466.77,7372.5 h60
  text "3.5" at 12116.6,7372.5 h60
  text "3" at 8787.5,7252.5 h60
  text "Layer 1 - Top Layer" at 9197.41,7252.5 h60
  text "Copper" at 10607,7252.5 h60
  text "1.40mil" at 11466.77,7252.5 h60
  text "4" at 8787.5,7132.5 h60
  text "Dielectric 1" at 9197.41,7132.5 h60
  text "370HR" at 10607,7132.5 h60
  text "5.20mil" at 11466.77,7132.5 h60
  text "4.2" at 12116.6,7132.5 h60
  text "5" at 8787.5,7012.5 h60
  text "Layer 2 - GND" at 9197.41,7012.5 h60
  text "Copper" at 10607,7012.5 h60
  text "1.42mil" at 11466.77,7012.5 h60
  text "6" at 8787.5,6892.5 h60
  text "Dielectric 2" at 9197.41,6892.5 h60
  text "370HR" at 10607,6892.5 h60
  text "43.00mil" at 11466.77,6892.5 h60
  text "4.2" at 12116.6,6892.5 h60
  text "7" at 8787.5,6772.5 h60
  text "Layer 3 - PWR" at 9197.41,6772.5 h60
  text "Copper" at 10607,6772.5 h60
  text "1.42mil" at 11466.77,6772.5 h60
  text "8" at 8787.5,6652.5 h60
  text "Dielectric 3" at 9197.41,6652.5 h60
  text "370HR" at 10607,6652.5 h60
  text "5.20mil" at 11466.77,6652.5 h60
  text "4.2" at 12116.6,6652.5 h60
  text "9" at 8787.5,6532.5 h60
  text "Layer 4 - Bottom Layer" at 9197.41,6532.5 h60
  text "Copper" at 10607,6532.5 h60
  text "1.40mil" at 11466.77,6532.5 h60
  text "10" at 8787.5,6412.5 h60
  text "Bottom Solder" at 9197.41,6412.5 h60
  text "Solder Resist" at 10607,6412.5 h60
  text "0.40mil" at 11466.77,6412.5 h60
  text "3.5" at 12116.6,6412.5 h60
  text "11" at 8787.5,6292.5 h60
  text "Bottom Overlay" at 9197.41,6292.5 h60
  text ".Layer_Name" at 57,-1078.49 h60
M13 Component Bodies Top:
  text ".Layer_Name" at 57,-1078.49 h60
M14 Component Bodies Bottom:
  text ".Layer_Name" at 57,-1078.49 h60
M15 Courtyards Top:
  text ".Layer_Name" at 57,-1078.49 h60
M16 Courtyards Bottom:
  text ".Layer_Name" at 57,-1078.49 h60
Drill Drawing:
  circle w10: c6503.8,549.33 r16.59
  circle w10: c6503.8,549.33 r27.66
  circle w10: c6503.8,300.41 r27.66
  lines w10: 6476.14,411.04 6489.97,411.04 6503.8,397.21 6517.63,411.04 6531.46,411.04 6517.63,424.87 6531.46,438.7 6517.63,438.7 6503.8,452.52 6489.97,438.7 6476.14,438.7 6489.97,424.87 6476.14,411.04 ; 6476.14,646.13 6531.46,646.13 6531.46,701.44 6476.14,701.44 6476.14,646.13 ; 6476.14,770.59 6476.14,784.41 6489.97,798.24 6476.14,812.07 6476.14,825.9 6489.97,825.9 6503.8,812.07 6517.63,825.9 6531.46,825.9 6531.46,812.07 6517.63,798.24 6531.46,784.41 6531.46,770.59 6517.63,770.59 6503.8,784.41 6489.97,770.59 6476.14,770.59 ; 6476.14,895.04 6531.46,895.04 6531.46,950.36 6476.14,950.36 6476.14,895.04 ; 6476.14,1033.33 6489.97,1033.33 6489.97,1019.5 6517.63,1019.5 6517.63,1033.33 6531.46,1033.33 6531.46,1060.99 6517.63,1060.99 6517.63,1074.82 6489.97,1074.82 6489.97,1060.99 6476.14,1060.99 6476.14,1033.33 ; 6476.14,1171.62 6503.8,1143.96 6531.46,1171.62 6503.8,1199.28 6476.14,1171.62 ; 6476.14,1268.42 6503.8,1282.25 6531.46,1268.42 6517.63,1296.08 6531.46,1323.74 6503.8,1309.91 6476.14,1323.74 6489.97,1296.08 6476.14,1268.42 ; 6487.21,906.11 6520.39,906.11 6520.39,939.3 6487.21,939.3 6487.21,906.11
  lines w12: 6426,235.41 10127.05,235.41 ; 6426,1355.54 10127.05,1355.54 ; 6764.17,110.95 6764.17,1480 ; 7096.28,110.95 7096.28,1480 ; 7733.29,110.95 7733.29,1480 ; 7992.64,110.95 7992.64,1480 ; 8368.06,110.95 8368.06,1480 ; 9560.2,110.95 9560.2,1480 ; 6426,110.95 10127.05,110.95 10127.05,1480 6426,1480 6426,110.95
  text "Symbol" at 6500.68,1392.88 h72
  text "Quantity" at 6801.51,1392.88 h72
  text "Finished Hole Size" at 7133.62,1392.88 h72
  text "Plated" at 7770.62,1392.88 h72
  text "Hole Type" at 8029.98,1392.88 h72
  text "Drill Layer Pair" at 8405.4,1392.88 h72
  text "Hole Tolerance" at 9597.54,1392.88 h72
  text "4" at 6801.51,1268.42 h60
  text "40.00mil (1.016mm)" at 7133.62,1268.42 h60
  text "NPTH" at 7770.62,1268.42 h60
  text "Round" at 8029.98,1268.42 h60
  text "Layer 1 - Top Layer - Layer 4 - Bottom Layer" at 8405.4,1268.42 h60
  text "4" at 6801.51,1143.96 h60
  text "173.23mil (4.400mm)" at 7133.62,1143.96 h60
  text "NPTH" at 7770.62,1143.96 h60
  text "Round" at 8029.98,1143.96 h60
  text "Layer 1 - Top Layer - Layer 4 - Bottom Layer" at 8405.4,1143.96 h60
  text "54" at 6801.51,1019.5 h60
  text "7.87mil (0.200mm)" at 7133.62,1019.5 h60
  text "PTH" at 7770.62,1019.5 h60
  text "Round" at 8029.98,1019.5 h60
  text "Layer 1 - Top Layer - Layer 4 - Bottom Layer" at 8405.4,1019.5 h60
  text "716" at 6801.51,895.04 h60
  text "10.00mil (0.254mm)" at 7133.62,895.04 h60
  text "PTH" at 7770.62,895.04 h60
  text "Round" at 8029.98,895.04 h60
  text "Layer 1 - Top Layer - Layer 4 - Bottom Layer" at 8405.4,895.04 h60
  text "23" at 6801.51,770.59 h60
  text "45.28mil (1.150mm)" at 7133.62,770.59 h60
  text "PTH" at 7770.62,770.59 h60
  text "Round" at 8029.98,770.59 h60
  text "Layer 1 - Top Layer - Layer 4 - Bottom Layer" at 8405.4,770.59 h60
  text "2" at 6801.51,646.13 h60
  text "51.18mil (1.300mm)" at 7133.62,646.13 h60
  text "PTH" at 7770.62,646.13 h60
  text "Round" at 8029.98,646.13 h60
  text "Layer 1 - Top Layer - Layer 4 - Bottom Layer" at 8405.4,646.13 h60
  text "4" at 6801.51,521.67 h60
  text "59.06mil (1.500mm)" at 7133.62,521.67 h60
  text "PTH" at 7770.62,521.67 h60
  text "Round" at 8029.98,521.67 h60
  text "Layer 1 - Top Layer - Layer 4 - Bottom Layer" at 8405.4,521.67 h60
  text "16" at 6801.51,397.21 h60
  text "66.93mil (1.700mm)" at 7133.62,397.21 h60
  text "PTH" at 7770.62,397.21 h60
  text "Round" at 8029.98,397.21 h60
  text "Layer 1 - Top Layer - Layer 4 - Bottom Layer" at 8405.4,397.21 h60
  text "4" at 6801.51,272.75 h60
  text "125.98mil (3.200mm)" at 7133.62,272.75 h60
  text "PTH" at 7770.62,272.75 h60
  text "Round" at 8029.98,272.75 h60
  text "Layer 1 - Top Layer - Layer 4 - Bottom Layer" at 8405.4,272.75 h60
  text "827 Total" at 6801.51,148.29 h60
  text ".Layer_Name" at 57,-1078.49 h60

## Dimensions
0,0 to 0,3930 on M2 Board Dimensions
0,0 to 4448,-1 on M2 Board Dimensions
-520,-620 to 480,-620 on M2 Board Dimensions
